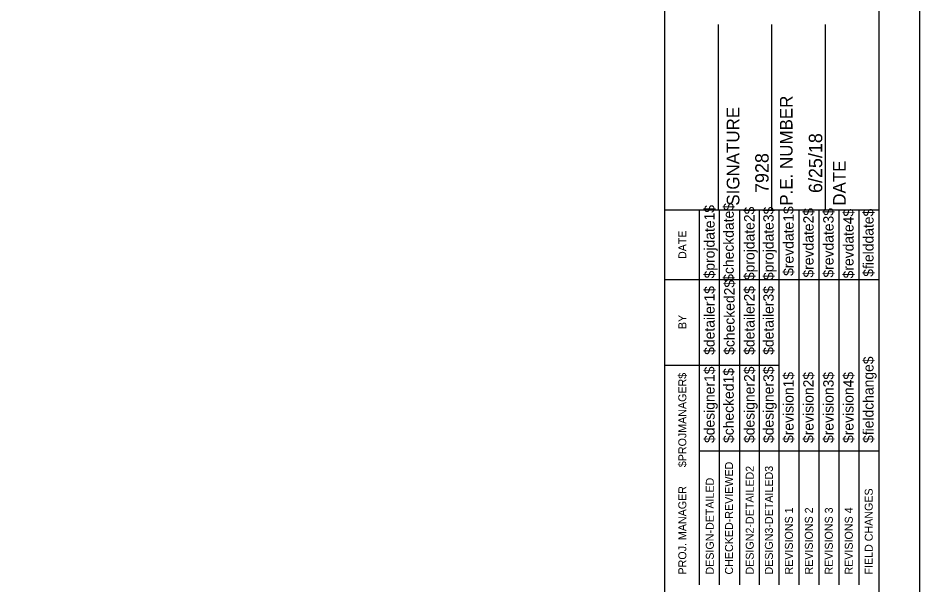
# Model space of a CAD drawing. Extents: x 916887 to 917745, y 329243 to 329793.
# Drawn here: x 917526.7 to 917737.2, y 329483 to 329615.2 of the extents above; entities that cross this region are included whole.
import ezdxf

# ---------------------------------------------------------------- set-up
doc = ezdxf.new("R2010")
doc.units = 0
doc.layers.add('Border', color=7, linetype='Continuous')
doc.layers.add('PLOT BOUNDARY', color=7, linetype='Continuous')

msp = doc.modelspace()

# ---------------------------------------------------------------- linework, layer by layer
at = {"layer": 'Border'}
for p, q in [((917677.63, 329258.01), (917677.63, 329783.01)), ((917727.63, 329258.01), (917727.63, 329783.01)), ((917690.13, 329570.51), (917690.13, 329613.75)), ((917702.63, 329570.51), (917702.63, 329613.75)), ((917715.13, 329570.51), (917715.13, 329613.75)), ((917677.63, 329570.51), (917727.63, 329570.51))]:
    msp.add_line(p, q, dxfattribs=at)
for points in [[(917685.71, 329554.26), (917685.71, 329570.51)], [(917690.37, 329483.03), (917690.37, 329570.51)], [(917695.03, 329570.51), (917695.03, 329483.03)], [(917699.69, 329483.03), (917699.69, 329570.51)], [(917704.34, 329483.03), (917704.34, 329570.51)], [(917709, 329483.03), (917709, 329570.51)], [(917713.66, 329483.03), (917713.66, 329570.51)], [(917718.32, 329483.03), (917718.32, 329570.51)], [(917722.98, 329483.03), (917722.98, 329570.51)], [(917685.71, 329483.03), (917685.71, 329566.98)], [(917677.63, 329554.26), (917727.63, 329554.26)], [(917677.63, 329534.26), (917685.71, 329534.26)], [(917685.71, 329534.26), (917704.34, 329534.26)], [(917685.71, 329514.26), (917727.63, 329514.26)]]:
    msp.add_lwpolyline(points, dxfattribs=at)
at = {"layer": 'PLOT BOUNDARY'}
msp.add_lwpolyline([(916887.17, 329242.7), (917737.16, 329242.7), (917737.16, 329792.7), (916887.17, 329792.7)], close=True, dxfattribs=at)

# ---------------------------------------------------------------- texts
at = {"layer": 'Border'}
for s, height, p in [('P.E. NUMBER', 2.9528, (917707.43, 329571.47)), ('SIGNATURE', 2.953, (917695.03, 329571.47)), ('6/25/18', 3.125, (917714.36, 329574.43)), ('7928', 3.125, (917701.86, 329574.43)), ('DATE', 2.953, (917719.84, 329571.47)), ('$checkdate$', 2.4227, (917693.72, 329553.72)), ('$projdate1$', 2.4227, (917689.25, 329554.51)), ('$projdate2$', 2.4227, (917698.56, 329554.12)), ('$projdate3$', 2.4227, (917703.03, 329554.12)), ('$revdate1$', 2.423, (917707.69, 329555.1)), ('$revdate2$', 2.423, (917712.35, 329554.71)), ('$revdate3$', 2.423, (917717.01, 329554.71)), ('$revdate4$', 2.423, (917721.67, 329554.51)), ('$fielddate$', 2.4227, (917726.33, 329554.9)), ('DATE', 1.857, (917682.65, 329559.04)), ('$checked2$', 2.423, (917693.9, 329536.69)), ('$detailer1$', 2.4227, (917689.25, 329536.69)), ('$detailer2$', 2.4227, (917698.56, 329536.69)), ('$detailer3$', 2.4227, (917703.03, 329536.69)), ('BY', 1.857, (917682.65, 329542.69)), ('$fieldchange$', 2.4227, (917726.33, 329516.13)), ('$PROJMANAGER$', 1.8637, (917682.65, 329510.48)), ('$designer1$', 2.4227, (917689.25, 329516.13)), ('$checked1$', 2.423, (917693.72, 329516.13)), ('$designer2$', 2.4227, (917698.56, 329516.13)), ('$designer3$', 2.4227, (917703.03, 329516.13)), ('$revision1$', 2.4227, (917707.69, 329516.13)), ('$revision2$', 2.4227, (917712.35, 329516.13)), ('$revision3$', 2.4227, (917717.01, 329516.13)), ('$revision4$', 2.4227, (917721.67, 329516.13)), ('CHECKED-REVIEWED', 1.8637, (917693.54, 329485.45)), ('DESIGN2-DETAILED2', 1.8637, (917698.38, 329485.45)), ('DESIGN3-DETAILED3', 1.8637, (917702.85, 329485.45)), ('DESIGN-DETAILED', 1.8637, (917689.06, 329485.45)), ('PROJ. MANAGER', 1.8637, (917682.65, 329485.45)), ('FIELD CHANGES', 1.8637, (917726.14, 329485.45)), ('REVISIONS 1', 1.8637, (917707.51, 329485.45)), ('REVISIONS 2', 1.8637, (917712.17, 329485.45)), ('REVISIONS 3', 1.8637, (917716.83, 329485.45)), ('REVISIONS 4', 1.8637, (917721.49, 329485.45))]:
    msp.add_text(s, height=height, rotation=90, dxfattribs=at).set_placement(p)

doc.saveas('drawing.dxf')
